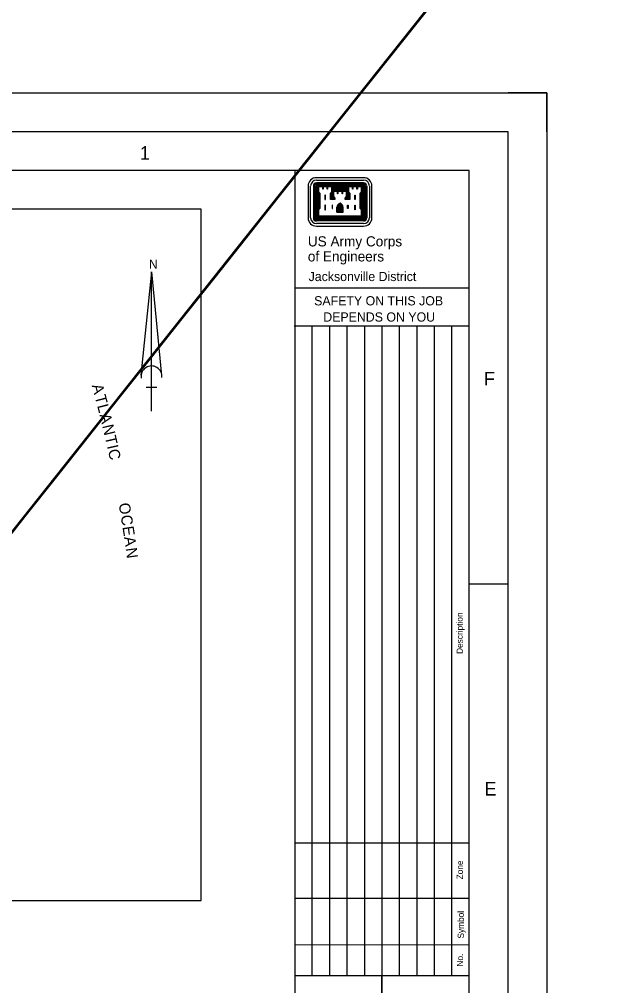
# Model space of a CAD drawing. Extents: x -42925 to 2366681, y -54064 to 2981876.
# Drawn here: x 696249 to 726584, y 853342 to 903190 of the extents above; entities that cross this region are included whole.
import ezdxf

# ---------------------------------------------------------------- set-up
doc = ezdxf.new("R2010")
doc.units = 0
for name, color, linetype in [('G-ANNO-NPLT', 7, 'Continuous'), ('G-ANNO-TEXT-LOGO', 7, 'Continuous'), ('G-ANNO-TEXT-TTLB', 7, 'Continuous'), ('G-ANNO-TTLB', 7, 'Continuous'), ('V-ANNO-SYMB', 7, 'Continuous')]:
    doc.layers.add(name, color=color, linetype=linetype)

msp = doc.modelspace()

# ---------------------------------------------------------------- linework, layer by layer
at = {"layer": 'G-ANNO-NPLT'}
msp.add_lwpolyline([(547448, 899395), (723447, 899395), (723447, 763396), (547448, 763396)], close=True, dxfattribs=at)
msp.add_lwpolyline([(723447, 897395), (723447, 899395), (721447, 899395)], dxfattribs=at)
at = {"layer": 'G-ANNO-TEXT-LOGO'}
for p, q in [((714001, 895020), (711569, 895020)), ((711569, 894892), (714001, 894892)), ((711141, 894592), (711141, 892952)), ((711269, 892952), (711269, 894592)), ((711409, 894592), (711409, 892952)), ((711445, 894592), (711445, 892952)), ((711477, 894592), (711477, 892952)), ((711513, 894592), (711513, 892952)), ((711549, 894592), (711549, 892952)), ((714001, 894756), (711569, 894756)), ((714001, 894720), (711569, 894720)), ((714001, 894684), (711569, 894684)), ((714001, 894652), (711569, 894652)), ((714001, 894616), (711569, 894616)), ((711585, 894592), (711585, 892964)), ((711617, 894592), (711617, 893000)), ((712413, 894584), (713157, 894584)), ((712413, 894548), (713157, 894548)), ((712413, 894516), (713157, 894516)), ((712413, 894480), (713157, 894480)), ((712413, 894444), (713157, 894444)), ((712413, 894412), (713157, 894412)), ((712413, 894376), (713157, 894376)), ((713953, 894592), (713953, 893000)), ((713985, 894592), (713985, 892964)), ((714021, 894592), (714021, 892952)), ((714057, 894592), (714057, 892952)), ((714089, 894592), (714089, 892952)), ((714125, 894592), (714125, 892952)), ((714161, 894592), (714161, 892952)), ((714297, 894592), (714297, 892952)), ((714429, 892952), (714429, 894592)), ((711645, 894244), (711645, 893404)), ((711681, 894208), (711681, 893444)), ((713889, 894208), (713889, 893444)), ((713925, 894240), (713925, 893408)), ((712625, 893236), (712625, 893504)), ((712657, 893236), (712657, 893504)), ((712693, 893236), (712693, 893504)), ((712729, 893236), (712729, 893504)), ((712761, 893236), (712761, 893504)), ((712809, 893236), (712809, 893504)), ((712841, 893236), (712841, 893504)), ((712877, 893236), (712877, 893504)), ((712913, 893236), (712913, 893504)), ((712945, 893236), (712945, 893504)), ((714001, 892928), (711569, 892928)), ((714001, 892896), (711569, 892896)), ((714001, 892860), (711569, 892860)), ((714001, 892824), (711569, 892824)), ((714001, 892792), (711569, 892792)), ((713985, 892964), (711585, 892964)), ((713953, 893000), (711617, 893000)), ((712625, 893236), (712945, 893236)), ((714001, 892652), (711569, 892652)), ((711569, 892520), (714001, 892520))]:
    msp.add_line(p, q, dxfattribs=at)
for points in [[(711645, 894592), (711645, 894276), (711713, 894208), (711713, 893444), (711645, 893372), (711645, 893024), (713925, 893024), (713925, 893372), (713853, 893444), (713853, 894208), (713925, 894276), (713925, 894592), (713625, 894592), (713393, 894592), (713177, 894592), (713177, 894276), (713253, 894208), (713253, 893928), (713085, 893928), (713085, 893956), (713157, 894028), (713157, 894340), (712857, 894340), (712625, 894340), (712413, 894340), (712413, 894028), (712485, 893956), (712485, 893928), (712317, 893928), (712317, 894208), (712389, 894276), (712389, 894592), (712089, 894592), (711857, 894592), (711645, 894592)], [(711677, 894556), (711677, 894292), (711749, 894220), (711749, 893428), (711677, 893356), (711677, 893060), (713893, 893060), (713893, 893356), (713817, 893428), (713817, 894220), (713893, 894292), (713893, 894556), (713677, 894556), (713677, 894432), (713657, 894432), (713657, 894556), (713445, 894556), (713445, 894432), (713429, 894432), (713429, 894556), (713213, 894556), (713213, 894292), (713285, 894220), (713285, 893896), (713053, 893896), (713053, 893972), (713125, 894044), (713125, 894308), (712909, 894308), (712909, 894184), (712893, 894184), (712893, 894308), (712677, 894308), (712677, 894184), (712657, 894184), (712657, 894308), (712445, 894308), (712445, 894044), (712517, 893972), (712517, 893896), (712285, 893896), (712285, 894220), (712357, 894292), (712357, 894556), (712145, 894556), (712145, 894432), (712125, 894432), (712125, 894556), (711909, 894556), (711909, 894432), (711893, 894432), (711893, 894556), (711677, 894556)], [(712005, 894128), (712005, 893896), (712029, 893896), (712029, 894128), (712005, 894128)], [(712373, 894212), (712353, 894192), (712353, 893964), (712429, 893964), (712377, 894016), (712377, 894216)], [(713197, 894212), (713217, 894192), (713217, 893964), (713145, 893964), (713193, 894016), (713193, 894216)], [(713561, 894128), (713561, 893896), (713541, 893896), (713541, 894128), (713561, 894128)], [(712005, 893596), (712005, 893360), (712029, 893360), (712029, 893596), (712005, 893596)], [(712373, 893596), (712373, 893432), (712393, 893432), (712393, 893596), (712373, 893596)], [(713197, 893596), (713197, 893432), (713177, 893432), (713177, 893596), (713197, 893596)], [(713561, 893596), (713561, 893360), (713541, 893360), (713541, 893596), (713561, 893596)]]:
    msp.add_lwpolyline(points, dxfattribs=at)
for centre, major_axis, start_param, end_param in [((711570, 894593), (429, 0), 1.57078, 3.141576), ((711570, 894593), (300, 0), 1.57078, 3.141576), ((713999, 894593), (429, 0), 6.283169, 7.853965), ((713999, 894593), (300, 0), 6.28317, 7.853966), ((711570, 894593), (161, 0), 1.57078, 3.141576), ((711570, 894593), (126, 0), 1.57078, 3.141576), ((711570, 894593), (91.3, 0), 1.57078, 3.141576), ((711570, 894593), (56.5, 0), 1.57078, 3.141576), ((711570, 894593), (21.8, 0), 1.57078, 3.141576), ((713999, 894593), (161, 0), 6.283169, 7.853965), ((713999, 894593), (126, 0), 6.283169, 7.853965), ((713999, 894593), (91.3, 0), 6.283169, 7.853965), ((713999, 894593), (56.5, 0), 6.283169, 7.853965), ((713999, 894593), (21.8, 0), 6.283169, 7.853965), ((712844, 893486), (-222, 0), 4.985832, 6.214359), ((712844, 893486), (-187, 0), 4.947465, 6.21436), ((712844, 893486), (-153, 0), 4.947465, 6.21436), ((712844, 893486), (-118, 0), 4.947465, 6.21436), ((712724, 893486), (83.3, 0), 0.068794, 1.335689), ((712724, 893486), (118, 0), 0.068794, 1.335689), ((712724, 893486), (153, 0), 0.068795, 1.335689), ((712844, 893486), (-83.3, 0), 4.947465, 6.214359), ((712724, 893486), (187, 0), 0.068795, 1.335689), ((712724, 893486), (222, 0), 0.068795, 1.29842), ((711570, 892950), (-429, 0), 6.28317, 7.853966), ((711570, 892950), (-300, 0), 6.28317, 7.853966), ((711570, 892950), (-161, 0), 6.28317, 7.853966), ((711570, 892950), (-126, 0), 6.28317, 7.853966), ((711570, 892950), (-91.3, 0), 6.28317, 7.853966), ((711570, 892950), (-56.5, 0), 6.28317, 7.853966), ((711570, 892950), (-21.8, 0), 6.28317, 7.853966), ((713999, 892950), (429, 0), 4.712373, 6.28317), ((713999, 892950), (-300, 0), 1.570781, 3.141577), ((713999, 892950), (161, 0), 4.712373, 6.28317), ((713999, 892950), (126, 0), 4.712373, 6.28317), ((713999, 892950), (91.3, 0), 4.712373, 6.28317), ((713999, 892950), (56.5, 0), 4.712373, 6.28317), ((713999, 892950), (21.8, 0), 4.712373, 6.28317)]:
    msp.add_ellipse(centre, major_axis=major_axis, ratio=0.99964, start_param=start_param, end_param=end_param, dxfattribs=at)
at = {"layer": 'G-ANNO-TTLB'}
for p, q in [((710446, 895395), (710446, 767396)), ((710447, 889346), (719447, 889346)), ((710422, 887381), (719422, 887381)), ((711339, 887381), (711339, 853865)), ((712239, 887381), (712239, 853865)), ((713139, 887381), (713139, 853865)), ((714039, 887381), (714039, 853865)), ((714939, 887381), (714939, 853865)), ((715839, 887381), (715839, 853865)), ((716739, 887381), (716739, 853865)), ((717639, 887381), (717639, 853865)), ((718539, 887381), (718539, 853865)), ((721447, 874055), (719447, 874055)), ((710447, 860706), (719447, 860706)), ((710447, 857859), (719447, 857859)), ((710447, 855459), (719447, 855457)), ((710447, 853865), (719447, 853865)), ((714920, 819482), (714947, 853865)), ((714947, 853865), (714946, 852448))]:
    msp.add_line(p, q, dxfattribs=at)
for points in [[(549448, 765396), (721447, 765396), (721447, 897395), (549448, 897395)], [(719447, 895395), (554448, 895395), (554448, 767396), (719447, 767396)]]:
    msp.add_lwpolyline(points, close=True, dxfattribs=at)
at = {"layer": 'V-ANNO-SYMB'}
for p, q in [((705617, 893395), (666104, 893395)), ((705617, 857744), (705617, 893395)), ((702527, 884826), (703083, 890168)), ((703064, 882970), (703064, 890170)), ((703602, 884822), (703080, 890172)), ((702792, 884212), (703332, 884212)), ((666104, 857744), (705617, 857744))]:
    msp.add_line(p, q, dxfattribs=at)
msp.add_arc((703064, 884770), 540, 353.3459, 188.7908, dxfattribs=at)
msp.add_spline([(691625, 871432), (691632, 871429), (691632, 871429), (691629, 871411), (691629, 871389), (691632, 871357)], degree=3, dxfattribs=at)

# ---------------------------------------------------------------- texts
at = {"layer": 'G-ANNO-TEXT-TTLB'}
for s, height, p in [('US Army Corps', 523.44, (711125, 891476)), ('of Engineers', 523.44, (711125, 890700)), ('Jacksonville District', 475.99, (711165, 889688)), ('SAFETY ON THIS JOB', 476, (711450, 888433)), ('DEPENDS ON YOU', 476, (711921, 887597))]:
    msp.add_text(s, height=height, dxfattribs=at).set_placement(p)
for s, p in [('Description', (719111, 870454)), ('Zone', (719123, 858826)), ('Symbol', (719170, 855773)), ('No.', (719130, 854328))]:
    msp.add_text(s, height=320, rotation=90, dxfattribs=at).set_placement(p)
at = {"layer": 'G-ANNO-TTLB'}
for s, p in [('1', (702463, 895949)), ('F', (720198, 884303)), ('E', (720229, 863149))]:
    msp.add_text(s, height=700, dxfattribs=at).set_placement(p)
at = {"layer": 'V-ANNO-SYMB'}
for s, height, rotation, p in [('N', 472, 0, (702927, 890329)), ('A', 576, 285.3188, (699978, 884298)), ('T', 576, 284.8034, (700131, 883738)), ('L', 576, 284.3674, (700257, 883263)), ('A', 576, 283.9315, (700380, 882786)), ('N', 576, 283.4161, (700520, 882222)), ('T', 576, 282.9008, (700654, 881657)), ('I', 576, 282.4648, (700764, 881177)), ('C', 576, 282.2667, (700813, 880959)), ('O', 576, 279.7701, (701364, 878198)), ('C', 576, 279.215, (701470, 877581)), ('E', 576, 278.6996, (701563, 877007)), ('A', 576, 278.2236, (701644, 876477)), ('N', 576, 277.7082, (701728, 875901))]:
    msp.add_text(s, height=height, rotation=rotation, dxfattribs=at).set_placement(p)

doc.saveas('drawing.dxf')
